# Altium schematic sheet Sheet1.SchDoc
size A4
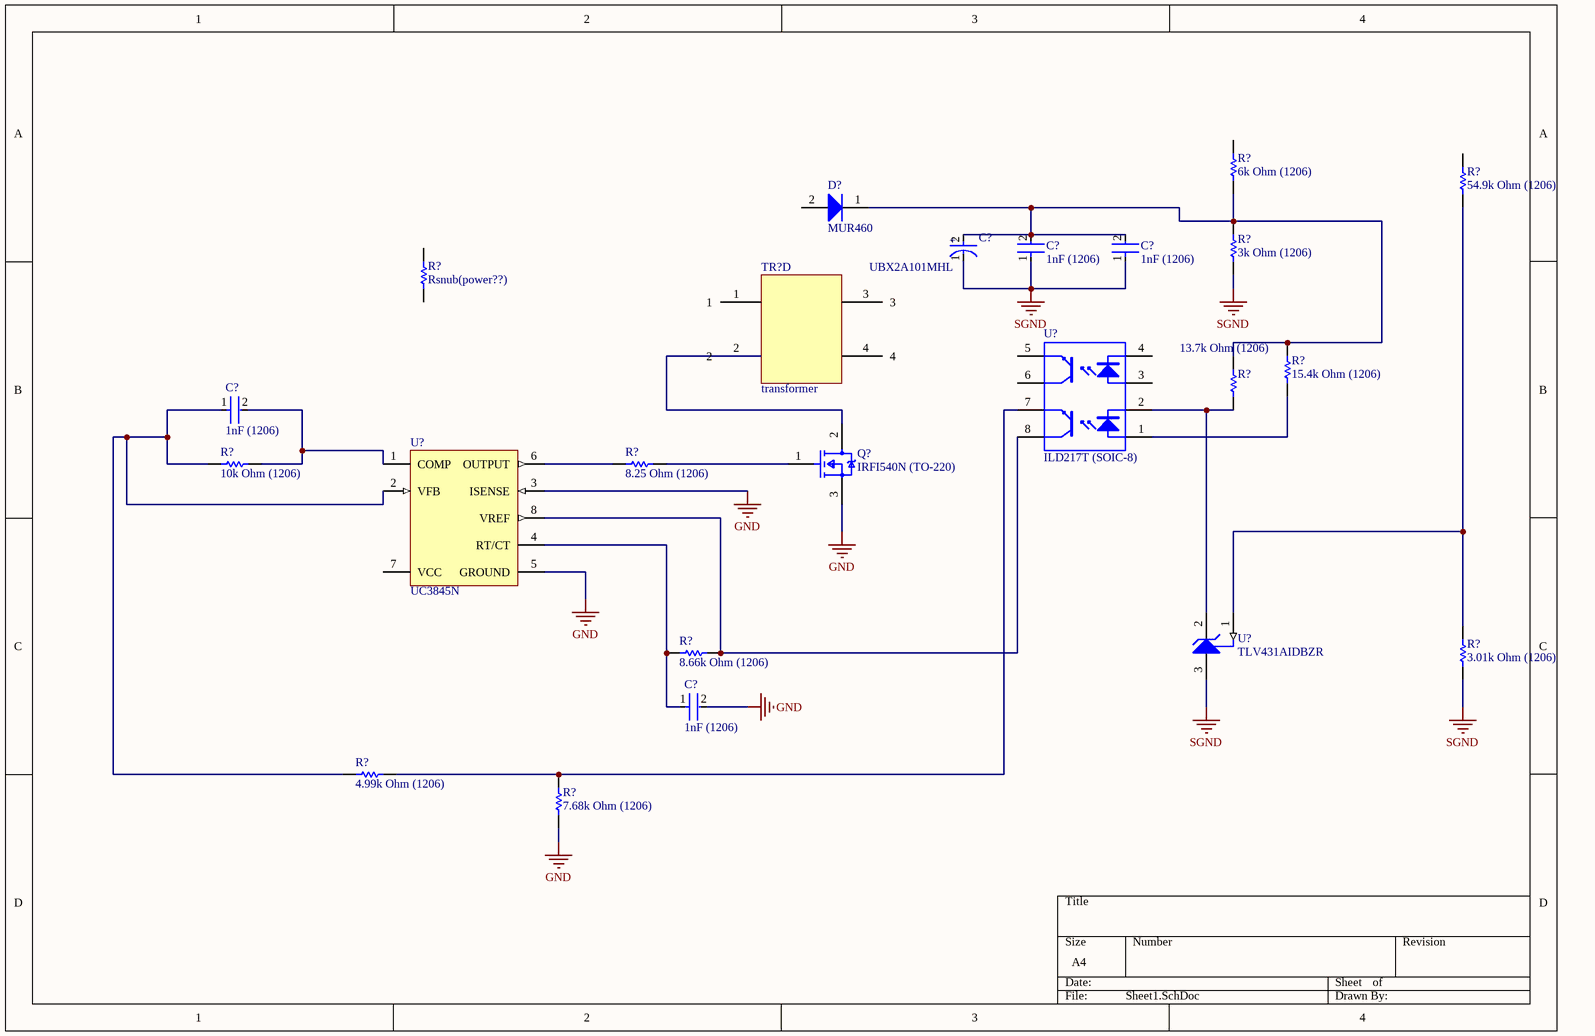
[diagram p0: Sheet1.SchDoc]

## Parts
(Parts that share a designator on the sheet are numbered #1, #2 ... from top to bottom, then left to right.)
C?#1  UBX2A101MHL  [FP-UBX2A101MHL-MFG]
C?#2  1nF (1206)  [FP-C1206C-EB-MFG]
C?#3  1nF (1206)  [FP-C1206C-EB-MFG]
C?#4  1nF (1206)  [FP-C1206C-EB-MFG]
C?#5  1nF (1206)  [FP-C1206C-EB-MFG]
D?  MUR460  [ONSC-AXIAL_LEAD-2-267-05_V]
Q?  IRFI540N (TO-220)  [FP-PG-TO220-3-MFG]
R?#1  6k Ohm (1206)  [RESC3216X60X45NL10T20]
R?#2  54.9k Ohm (1206)  [RESC3216X60X45NL10T20]
R?#3  3k Ohm (1206)  [RESC3216X60X45NL10T20]
R?#4  Rsnub(power??)  [RESC3216X60X45NL10T20]
R?#5  15.4k Ohm (1206)  [RESC3216X60X45NL10T20]
R?#6  13.7k Ohm (1206)  [RESC3216X60X45NL10T20]
R?#7  8.25 Ohm (1206)  [RESC3216X60X45NL10T20]
R?#8  10k Ohm (1206)  [RESC3216X60X45NL10T20]
R?#9  3.01k Ohm (1206)  [RESC3216X60X45NL10T20]
R?#10  8.66k Ohm (1206)  [RESC3216X60X45NL10T20]
R?#11  4.99k Ohm (1206)  [RESC3216X60X45NL10T20]
R?#12  7.68k Ohm (1206)  [RESC3216X60X45NL10T20]
TR?  transformer  [Transformer_flyback]  (part D of 4)
U?#1  UC3845N  [P0008A]
U?#2  ILD217T (SOIC-8)  [VISH-SOIC-8_C_V]
U?#3  TLV431AIDBZR  [DBZ0003A_N]

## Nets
GND: C?#5.2 Q?.3(S) R?#12.1 U?#1.3(ISENSE) U?#1.5(GROUND)
SGND: C?#1.1(C) C?#2.1 C?#3.1 R?#3.2 R?#9.2 U?#3.3(ANODE)
NetC?#1_2: C?#1.2(A) C?#2.2 C?#3.2 D?.1(K) R?#1.2 R?#3.1 R?#5.1 R?#6.1
NetC?#4_1: C?#4.1 R?#8.2 R?#11.2 U?#1.2(VFB)
NetC?#4_2: C?#4.2 R?#8.1 U?#1.1(COMP)
NetC?#5_1: C?#5.1 R?#10.2 U?#1.4(RT/CT)
NetQ?_1: Q?.1(G) R?#7.2
NetQ?_2: Q?.2(D) TR?.2
NetR?#2_2: R?#2.2 R?#9.1 U?#3.1(REF)
NetR?#5_2: R?#5.2 U?#2.1(A)
NetR?#6_2: R?#6.2 U?#2.2(K) U?#3.2(CATHODE)
NetR?#7_1: R?#7.1 U?#1.6(OUTPUT)
NetR?#10_1: R?#10.1 U?#1.8(VREF) U?#2.8(C)
NetR?#11_1: R?#11.1 R?#12.2 U?#2.7(E)

Not connected (* = marked no-connect by the designer): D? 2(A); R?#1 1; R?#2 1; R?#4 1 2; TR? 1 3 4; U?#1 7(VCC); U?#2 3(A) 4(K) 5(E) 6(C)

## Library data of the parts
C?#1 = CMP-12462-000004-1: CAP ALUM 100UF 20% 100V RADIAL; Manufacturer: Nichicon; Material: Aluminum; Automotive Grade: Grade 0; Ripple Current: 950mA; Leakage Current: 300uA; Life: 1000Hours; Dissipation Factor: 8%
C?#2-C?#5 = CMP-03020-000955-1: Multilayer Ceramic Capacitor, C Series, 1000 Pf, - 5%, C0g / Np0, 100 V, 1206 [3216 Metric] Rohs Compliant: Yes; Manufacturer: KEMET; Manufacturer Part Number: C1206C102J1GACTU; Capacitance: 1,000 pF; Voltage Rating: 100 V; Tolerance: 0.05; Automotive Grade: Grade 0; Temperature Coefficient: 15%; Value: 1,000 pF
D? = CMP-0902-00067-1: SWITCHMODE(TM) Power Rectifier, 2-Pin Axial_Lead, Pb-Free, Bulk Bag; Manufacturer: On Semiconductor; IFSM Max (A): 110; Type: Ultrafast; VRRM Max (V): 600
Q? = CMP-32901-000575-1: MOSFET N-CH 100V 20A TO220FP; Gate to Source Voltage (Vgs): 20V; Power Dissipation: 54W; Rds On Max: 52mR; Threshold Voltage: 4V; Turn-On Delay Time: 8.2ns; Turn-Off Delay Time: 44ns; Input Capacitance: 1.4nF; Element Configuration: Single
R?#1-R?#12 = CMP-2003-02424-1: Manufacturer: Vishay Dale; Part Number: CRCW12068R25FKEA
U?#1 = CMP-0319-00305-2: PWM Controller with Current Control, 50 % Duty Cycle, 0 to +70 degC, 8-pin PDIP (P), Green (RoHS & no Sb/Br); Manufacturer: Texas Instruments; Rating: Catalog; UVLO Thresholds On/Off(V): 8.4/7.6; Regulated Outputs(#): 1; Duty Cycle(Max)(%): 50; Frequency(Max)(kHz): 450; Topology: Boost, Buck, Flyback, Forward
U?#2 = CMP-2000-06453-1: Optocoupler, Phototransistor Output, Dual Channel, 4000 VRMS, -55 to 100 degC, 8-Pin SOIC, RoHS, Tape and Reel; Manufacturer: Vishay; Voltage - Output (Max): 70V; Vce Saturation (Max): 400mV; Number of Channels: 2; Voltage - Forward (Vf) (Typ): 1.2V; EDA / CAD Models: DownloadfromAcceleratedDesigns; Current Transfer Ratio (Min): 100%@10mA; Current Transfer Ratio (Max): 200%@10mA; Input Type: DC; Current - DC Forward (If) (Max): 30mA; Rise / Fall Time (Typ): 3µs,4.7µs; Turn On / Turn Off Time (Typ): 6µs,5µs; Catalog Drawings: OptocouplerCircuit; Other Names: 751-1310-1ILD207TGICTILD207TGICT-ND; Online Catalog: ILD205T,206T,207T,211T,213T,217TSeries
U?#3 = CMP-0366-00975-2: Low Voltage Adjustable Precision Shunt Regulator, 39 ppm / degC, 15 mA, -40 to 85 degC, 3-pin SOT-23 (DBZ), Green (RoHS & no Sb/Br); Manufacturer: Texas Instruments; Temp Coeff(Typ)(ppm/ degree C): 39; VO Adj(Max)(V): 6; SubFamily: Shunt Voltage Reference; Min Iz for Regulation(uA): 80; Temp Coeff(Max)(ppm/ degree C): 129; VO Adj(Min)(V): 1.24; Initial Accuracy @ 25/deg C(%): 1; Iout/Iz(Max)(mA): 15; Rating: Catalog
